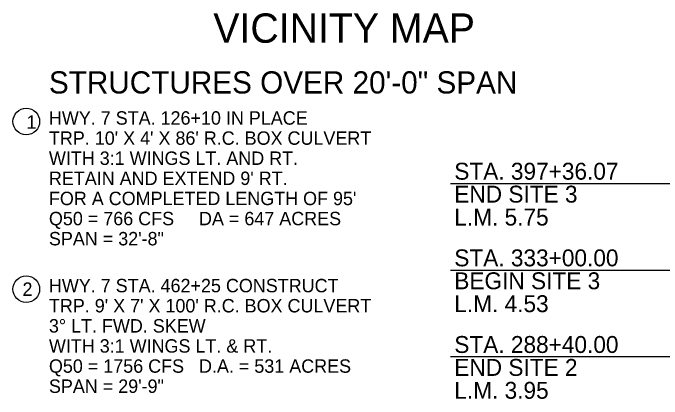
# Model space of a CAD drawing. Extents: x 1373862 to 1377080, y 1164775 to 1170415.
# Drawn here: x 1373874 to 1374641, y 1169401 to 1169858 of the extents above; entities that cross this region are included whole.
import ezdxf

# ---------------------------------------------------------------- set-up
doc = ezdxf.new("R2010")
doc.units = 0
for name, color, linetype in [('2', 7, 'Continuous'), ('21', 7, 'Continuous'), ('R_Dimension', 7, 'Continuous')]:
    doc.layers.add(name, color=color, linetype=linetype)

msp = doc.modelspace()

# ---------------------------------------------------------------- linework, layer by layer
at = {"layer": '21'}
for centre in [(1373889.84, 1169729.21), (1373889.84, 1169531.03)]:
    msp.add_circle(centre, 15.74, dxfattribs=at)
at = {"layer": 'R_Dimension'}
for p, q in [((1374391.28, 1169656.09), (1374671.71, 1169656.09)), ((1374391.28, 1169553.67), (1374671.71, 1169553.67)), ((1374391.28, 1169451.25), (1374671.71, 1169451.25))]:
    msp.add_line(p, q, dxfattribs=at)

# ---------------------------------------------------------------- texts
at = {"layer": '2'}
msp.add_text('VICINITY MAP', height=34.6828, dxfattribs=at).set_placement((1374110.86, 1169822.36))
at = {"layer": '21'}
for s, height, p in [('STRUCTURES OVER 20\'-0" SPAN', 26.25, (1373916.58, 1169762.34)), ('HWY. 7 STA. 126+10 IN PLACE', 15.855, (1373916.58, 1169725.5)), ('1', 15.85, (1373890.03, 1169720.72)), ("TRP. 10' X 4' X 86' R.C. BOX CULVERT", 15.855, (1373916.58, 1169701.72)), ('WITH 3:1 WINGS LT. AND RT.', 15.855, (1373916.58, 1169677.94)), ("RETAIN AND EXTEND 9' RT. ", 15.855, (1373916.58, 1169654.16)), ("FOR A COMPLETED LENGTH OF 95'", 15.855, (1373916.58, 1169630.37)), ('Q50 = 766 CFS     DA = 647 ACRES', 15.855, (1373916.58, 1169606.59)), ('SPAN = 32\'-8"', 15.855, (1373916.58, 1169582.81)), ('2', 15.85, (1373885.34, 1169523.1)), ('HWY. 7 STA. 462+25 CONSTRUCT', 15.855, (1373916.58, 1169527.32)), ("TRP. 9' X 7' X 100' R.C. BOX CULVERT", 15.855, (1373916.58, 1169503.53)), ('3%%D LT. FWD. SKEW', 15.855, (1373916.58, 1169479.75)), ('WITH 3:1 WINGS LT. & RT.', 15.855, (1373916.58, 1169455.97)), ('Q50 = 1756 CFS   D.A. = 531 ACRES', 15.855, (1373916.58, 1169432.19)), ('SPAN = 29\'-9"', 15.855, (1373916.58, 1169408.4))]:
    msp.add_text(s, height=height, dxfattribs=at).set_placement(p)
at = {"layer": 'R_Dimension'}
for s, p in [('STA. 397+36.07', (1374395.67, 1169660.45)), ('END SITE 3', (1374395.67, 1169633.36)), ('L.M. 5.75', (1374395.67, 1169606.26)), ('STA. 333+00.00', (1374395.67, 1169558.03)), ('BEGIN SITE 3', (1374395.67, 1169530.94)), ('L.M. 4.53', (1374395.67, 1169503.84)), ('STA. 288+40.00', (1374395.67, 1169455.61)), ('END SITE 2', (1374395.67, 1169428.52)), ('L.M. 3.95', (1374395.67, 1169401.42))]:
    msp.add_text(s, height=20, rotation=0.0006, dxfattribs=at).set_placement(p)

doc.saveas('drawing.dxf')
